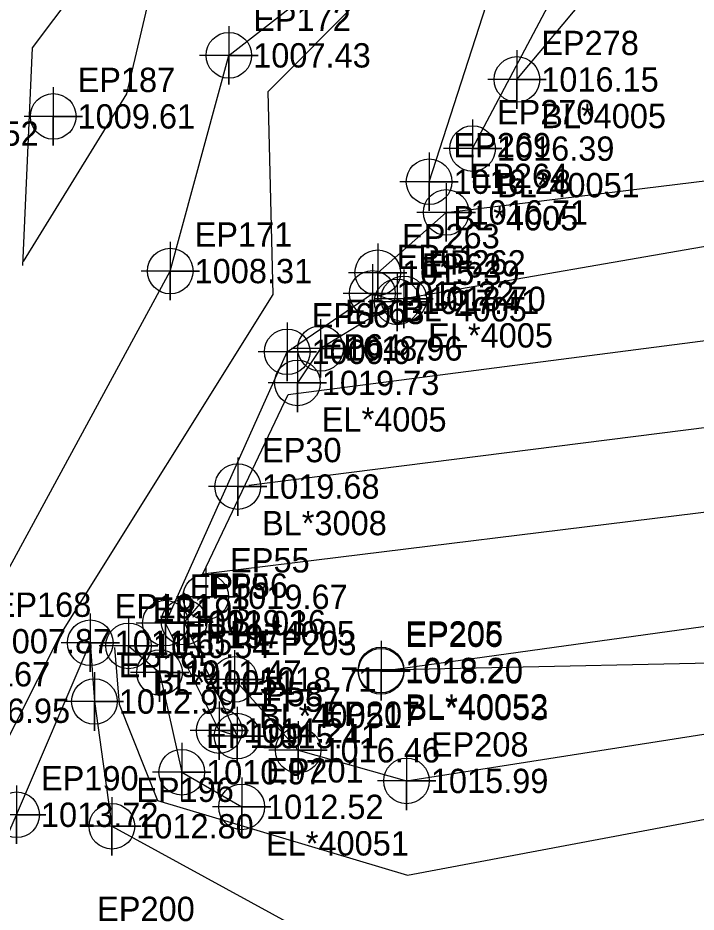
# Model space of a CAD drawing. Extents: x 1382561 to 1383039, y 884068 to 884307.
# Drawn here: x 1382794.3 to 1382864, y 884154.1 to 884246 of the extents above; entities that cross this region are included whole.
import ezdxf

# ---------------------------------------------------------------- set-up
doc = ezdxf.new("R2010")
doc.units = 0
for name, color, linetype in [('Exist DTM Breakline', 7, 'Continuous'), ('Exist DTM Breakline Cogo Comment', 7, 'Continuous'), ('Exist DTM Breakline Cogo Elevation', 7, 'Continuous'), ('Exist DTM Breakline Cogo Number', 7, 'Continuous'), ('Exist DTM Breakline Cogo Point CELL', 7, 'Continuous'), ('Exist DTM Breakline Underwater', 7, 'Continuous'), ('Exist DTM Breakline Underwater Cogo Elevation', 7, 'Continuous'), ('Exist DTM Breakline Underwater Cogo Number', 7, 'Continuous'), ('Exist DTM Breakline Underwater Cogo Point CELL', 7, 'Continuous'), ('Exist DTM Crownline', 7, 'Continuous'), ('Exist DTM Crownline Cogo Comment', 7, 'Continuous'), ('Exist DTM Crownline Cogo Elevation', 7, 'Continuous'), ('Exist DTM Crownline Cogo Number', 7, 'Continuous'), ('Exist DTM Crownline Cogo Point CELL', 7, 'Continuous'), ('Exist DTM Regular Point CELL', 7, 'Continuous'), ('Exist DTM Regular Point Cogo Elevation', 7, 'Continuous'), ('Exist DTM Regular Point Cogo Number', 7, 'Continuous'), ('Exist Hydro Stream or Body of Water', 7, 'Continuous'), ('Exist Roads EOP', 7, 'Continuous')]:
    doc.layers.add(name, color=color, linetype=linetype)

msp = doc.modelspace()

# ---------------------------------------------------------------- linework, layer by layer
at = {"layer": 'Exist DTM Breakline'}
msp.add_line((1382845.6099, 884239.6486), (1382877.4407, 884277.6733), dxfattribs=at)
for points in [[(1382836.5882, 884229.1511), (1382845.3839, 884256.4006), (1382857.665, 884285.1804)], [(1382841.0523, 884232.5474), (1382851.5055, 884252.2797), (1382873.9304, 884278.5226)], [(1382831.3079, 884219.8003), (1382838.3409, 884225.9989), (1382867.1646, 884229.517), (1382914.9927, 884234.9104), (1382969.1885, 884241.9138), (1383012.0651, 884249.1214)], [(1383012.5976, 884239.5988), (1382967.445, 884235.5084), (1382916.3525, 884229.3577), (1382867.9342, 884223.0248), (1382833.9892, 884217.1167)], [(1382813.6347, 884186.5142), (1382811.4039, 884183.9166), (1382816.8445, 884172.2048), (1382815.0173, 884172.7731), (1382809.4772, 884183.8181), (1382822.0049, 884211.6766), (1382830.7533, 884217.6734), (1382833.3088, 884216.8097), (1382825.4375, 884212.0253), (1382823.0555, 884208.4903)], [(1382831.6499, 884178.864), (1382874.1379, 884184.7558), (1382926.2901, 884192.0506), (1382972.0132, 884197.818), (1383015.5779, 884204.7229)], [(1382833.366, 884179.0369), (1382875.2238, 884179.95), (1382925.7486, 884188.0979), (1382971.8534, 884193.2925), (1383016.146, 884199.3057)], [(1382816.5885, 884178.0325), (1382823.1269, 884170.7527), (1382834.2668, 884167.6062), (1382876.3893, 884174.2104), (1382925.471, 884179.9339), (1382972.4064, 884189.3415), (1383016.1626, 884195.7946)], [(1382751.4287, 884075.9856), (1382771.8716, 884111.3375), (1382784.8942, 884142.8663), (1382794.19, 884164.1279), (1382801.7626, 884181.793), (1382802.1903, 884175.7622), (1382803.9822, 884162.9447), (1382834.7331, 884146.1448), (1382885.2227, 884156.817), (1382912.2708, 884159.0791), (1382962.484, 884168.5252), (1383014.0488, 884181.852)], [(1382805.6901, 884181.4753), (1382808.8901, 884178.7339), (1382811.1624, 884168.5017), (1382817.3226, 884164.9432)]]:
    msp.add_lwpolyline(points, dxfattribs=at)
at = {"layer": 'Exist DTM Breakline Cogo Point CELL'}
for points in [[(1382845.6099, 884242.6486), (1382845.6099, 884236.6486), (1382845.6099, 884239.6486), (1382848.6099, 884239.6486), (1382842.6099, 884239.6486)], [(1382841.0523, 884235.5474), (1382841.0523, 884229.5474), (1382841.0523, 884232.5474), (1382844.0523, 884232.5474), (1382838.0523, 884232.5474)], [(1382836.5882, 884232.1511), (1382836.5882, 884226.1511), (1382836.5882, 884229.1511), (1382839.5882, 884229.1511), (1382833.5882, 884229.1511)], [(1382838.3409, 884228.9989), (1382838.3409, 884222.9989), (1382838.3409, 884225.9989), (1382841.3409, 884225.9989), (1382835.3409, 884225.9989)], [(1382831.3079, 884222.8003), (1382831.3079, 884216.8003), (1382831.3079, 884219.8003), (1382834.3079, 884219.8003), (1382828.3079, 884219.8003)], [(1382830.7533, 884220.6734), (1382830.7533, 884214.6734), (1382830.7533, 884217.6734), (1382833.7533, 884217.6734), (1382827.7533, 884217.6734)], [(1382833.3088, 884219.8097), (1382833.3088, 884213.8097), (1382833.3088, 884216.8097), (1382836.3088, 884216.8097), (1382830.3088, 884216.8097)], [(1382833.9892, 884220.1167), (1382833.9892, 884214.1167), (1382833.9892, 884217.1167), (1382836.9892, 884217.1167), (1382830.9892, 884217.1167)], [(1382822.0049, 884214.6766), (1382822.0049, 884208.6766), (1382822.0049, 884211.6766), (1382825.0049, 884211.6766), (1382819.0049, 884211.6766)], [(1382825.4375, 884215.0253), (1382825.4375, 884209.0253), (1382825.4375, 884212.0253), (1382828.4375, 884212.0253), (1382822.4375, 884212.0253)], [(1382823.0555, 884211.4903), (1382823.0555, 884205.4903), (1382823.0555, 884208.4903), (1382826.0555, 884208.4903), (1382820.0555, 884208.4903)], [(1382813.6347, 884189.5142), (1382813.6347, 884183.5142), (1382813.6347, 884186.5142), (1382816.6347, 884186.5142), (1382810.6347, 884186.5142)], [(1382809.4772, 884186.8181), (1382809.4772, 884180.8181), (1382809.4772, 884183.8181), (1382812.4772, 884183.8181), (1382806.4772, 884183.8181)], [(1382811.4039, 884186.9166), (1382811.4039, 884180.9166), (1382811.4039, 884183.9166), (1382814.4039, 884183.9166), (1382808.4039, 884183.9166)], [(1382801.7626, 884184.793), (1382801.7626, 884178.793), (1382801.7626, 884181.793), (1382804.7626, 884181.793), (1382798.7626, 884181.793)], [(1382805.6901, 884184.4753), (1382805.6901, 884178.4753), (1382805.6901, 884181.4753), (1382808.6901, 884181.4753), (1382802.6901, 884181.4753)], [(1382808.8901, 884181.7339), (1382808.8901, 884175.7339), (1382808.8901, 884178.7339), (1382811.8901, 884178.7339), (1382805.8901, 884178.7339)], [(1382831.6443, 884181.9993), (1382831.6443, 884175.9993), (1382831.6443, 884178.9993), (1382834.6443, 884178.9993), (1382828.6443, 884178.9993)], [(1382831.6499, 884181.864), (1382831.6499, 884175.864), (1382831.6499, 884178.864), (1382834.6499, 884178.864), (1382828.6499, 884178.864)], [(1382816.5885, 884181.0325), (1382816.5885, 884175.0325), (1382816.5885, 884178.0325), (1382819.5885, 884178.0325), (1382813.5885, 884178.0325)], [(1382802.1903, 884178.7622), (1382802.1903, 884172.7622), (1382802.1903, 884175.7622), (1382805.1903, 884175.7622), (1382799.1903, 884175.7622)], [(1382815.0173, 884175.7731), (1382815.0173, 884169.7731), (1382815.0173, 884172.7731), (1382818.0173, 884172.7731), (1382812.0173, 884172.7731)], [(1382816.8445, 884175.2048), (1382816.8445, 884169.2048), (1382816.8445, 884172.2048), (1382819.8445, 884172.2048), (1382813.8445, 884172.2048)], [(1382823.1269, 884173.7527), (1382823.1269, 884167.7527), (1382823.1269, 884170.7527), (1382826.1269, 884170.7527), (1382820.1269, 884170.7527)], [(1382811.1624, 884171.5017), (1382811.1624, 884165.5017), (1382811.1624, 884168.5017), (1382814.1624, 884168.5017), (1382808.1624, 884168.5017)], [(1382834.2668, 884170.6062), (1382834.2668, 884164.6062), (1382834.2668, 884167.6062), (1382837.2668, 884167.6062), (1382831.2668, 884167.6062)], [(1382817.3226, 884167.9432), (1382817.3226, 884161.9432), (1382817.3226, 884164.9432), (1382820.3226, 884164.9432), (1382814.3226, 884164.9432)], [(1382794.19, 884167.1279), (1382794.19, 884161.1279), (1382794.19, 884164.1279), (1382797.19, 884164.1279), (1382791.19, 884164.1279)], [(1382803.9822, 884165.9447), (1382803.9822, 884159.9447), (1382803.9822, 884162.9447), (1382806.9822, 884162.9447), (1382800.9822, 884162.9447)]]:
    msp.add_lwpolyline(points, dxfattribs=at)
for centre in [(1382845.6099, 884239.6486), (1382841.0523, 884232.5474), (1382836.5882, 884229.1511), (1382838.3409, 884225.9989), (1382831.3079, 884219.8003), (1382830.7533, 884217.6734), (1382833.3088, 884216.8097), (1382833.9892, 884217.1167), (1382825.4375, 884212.0253), (1382822.0049, 884211.6766), (1382823.0555, 884208.4903), (1382813.6347, 884186.5142), (1382809.4772, 884183.8181), (1382811.4039, 884183.9166), (1382801.7626, 884181.793), (1382805.6901, 884181.4753), (1382831.6443, 884178.9993), (1382831.6499, 884178.864), (1382808.8901, 884178.7339), (1382816.5885, 884178.0325), (1382802.1903, 884175.7622), (1382815.0173, 884172.7731), (1382816.8445, 884172.2048), (1382823.1269, 884170.7527), (1382811.1624, 884168.5017), (1382834.2668, 884167.6062), (1382817.3226, 884164.9432), (1382794.19, 884164.1279), (1382803.9822, 884162.9447)]:
    msp.add_circle(centre, 2.344, dxfattribs=at)
at = {"layer": 'Exist DTM Breakline Underwater'}
msp.add_lwpolyline([(1382688.3783, 884086.9383), (1382699.504, 884112.5821), (1382721.2073, 884133.5617), (1382743.6214, 884142.6712), (1382769.5658, 884160.0329), (1382785.1067, 884174.8132), (1382789.3291, 884181.9565), (1382809.982, 884219.9732), (1382816.0046, 884242.1273), (1382837.3981, 884258.7844), (1382845.6113, 884276.5289)], dxfattribs=at)
at = {"layer": 'Exist DTM Breakline Underwater Cogo Point CELL'}
for points in [[(1382816.0046, 884245.1273), (1382816.0046, 884239.1273), (1382816.0046, 884242.1273), (1382819.0046, 884242.1273), (1382813.0046, 884242.1273)], [(1382809.982, 884222.9732), (1382809.982, 884216.9732), (1382809.982, 884219.9732), (1382812.982, 884219.9732), (1382806.982, 884219.9732)]]:
    msp.add_lwpolyline(points, dxfattribs=at)
for centre in [(1382816.0046, 884242.1273), (1382809.982, 884219.9732)]:
    msp.add_circle(centre, 2.344, dxfattribs=at)
at = {"layer": 'Exist DTM Crownline'}
msp.add_lwpolyline([(1382818.0568, 884197.9832), (1382870.8354, 884204.6592), (1382920.1217, 884211.0486), (1382969.977, 884216.8417), (1383014.7296, 884222.2543)], dxfattribs=at)
at = {"layer": 'Exist DTM Crownline Cogo Point CELL'}
msp.add_lwpolyline([(1382816.9119, 884200.8384), (1382816.9119, 884194.8384), (1382816.9119, 884197.8384), (1382819.9119, 884197.8384), (1382813.9119, 884197.8384)], dxfattribs=at)
msp.add_circle((1382816.9119, 884197.8384), 2.344, dxfattribs=at)
at = {"layer": 'Exist DTM Regular Point CELL'}
msp.add_lwpolyline([(1382797.9522, 884238.8572), (1382797.9522, 884232.8572), (1382797.9522, 884235.8572), (1382800.9522, 884235.8572), (1382794.9522, 884235.8572)], dxfattribs=at)
msp.add_circle((1382797.9522, 884235.8572), 2.344, dxfattribs=at)
at = {"layer": 'Exist Hydro Stream or Body of Water'}
for points in [[(1382697.0874, 884084.7019), (1382707.0296, 884107.5273), (1382718.101, 884120.6229), (1382747.1797, 884135.9958), (1382776.4132, 884151.3238), (1382791.7634, 884168.9711), (1382798.6691, 884182.5745), (1382820.5432, 884217.5751), (1382820.037, 884238.4145), (1382839.3094, 884257.7694), (1382850.1603, 884274.5827)], [(1382811.148, 884263.3209), (1382795.7798, 884242.8831), (1382794.8118, 884220.542)], [(1382811.3728, 884263.1874), (1382805.484, 884238.1799), (1382794.8471, 884220.9683)], [(1382804.2469, 884181.3186), (1382804.7285, 884175.5016), (1382808.6563, 884165.6118), (1382834.3787, 884157.9417), (1382885.1736, 884167.4669), (1382917.5577, 884168.9128), (1382957.8255, 884179.6802), (1383014.491, 884188.8061)]]:
    msp.add_lwpolyline(points, dxfattribs=at)
at = {"layer": 'Exist Roads EOP'}
for points in [[(1382822.1133, 884207.287), (1382869.4756, 884213.4311), (1382919.3634, 884219.5355), (1382969.3733, 884225.6957), (1383013.6331, 884231.1593)], [(1382813.3303, 884188.8665), (1382871.1957, 884195.987), (1382921.2905, 884202.1311), (1382970.8421, 884208.1022), (1383015.6768, 884213.5139)], [(1382813.3303, 884188.8665), (1382822.1133, 884207.287)]]:
    msp.add_lwpolyline(points, dxfattribs=at)

# ---------------------------------------------------------------- texts
at = {"layer": 'Exist DTM Breakline Cogo Comment'}
for s, p in [('BL*4005', (1382848.1099, 884234.6486)), ('BL*40051', (1382843.5523, 884227.5474)), ('BL*4005', (1382839.0882, 884224.1511)), ('BL*4005', (1382833.8079, 884214.8003)), ('EL*4005', (1382836.4892, 884212.1167)), ('EL*4005', (1382825.5555, 884203.4903)), ('BL*4005', (1382816.1347, 884181.5142)), ('BL*40051', (1382808.1901, 884176.4753)), ('BL*40052', (1382834.1443, 884173.9993)), ('BL*40053', (1382834.1499, 884173.864)), ('BL*40051', (1382819.0885, 884173.0325)), ('EL*40051', (1382819.8226, 884159.9432))]:
    msp.add_text(s, height=2.5, dxfattribs=at).set_placement(p)
at = {"layer": 'Exist DTM Breakline Cogo Elevation'}
for s, p in [('1016.15', (1382848.1099, 884238.3986)), ('1014.52', (1382784.3725, 884232.8418)), ('1016.39', (1382843.5523, 884231.2974)), ('1016.28', (1382839.0882, 884227.9011)), ('1016.71', (1382840.8409, 884224.7489)), ('1015.39', (1382833.8079, 884218.5503)), ('1015.22', (1382833.2533, 884216.4234)), ('1017.41', (1382835.8088, 884215.5597)), ('1018.70', (1382836.4892, 884215.8667)), ('1009.97', (1382824.5049, 884210.4266)), ('1018.96', (1382827.9375, 884210.7753)), ('1019.73', (1382825.5555, 884207.2403)), ('1019.67', (1382816.1347, 884185.2642)), ('1012.03', (1382811.9772, 884182.5681)), ('1019.16', (1382813.9039, 884182.6666)), ('1011.65', (1382804.2626, 884180.543)), ('1010.54', (1382808.1901, 884180.2253)), ('1018.20', (1382834.1443, 884177.7493)), ('1011.47', (1382811.3901, 884177.4839)), ('1018.20', (1382834.1499, 884177.614)), ('1018.71', (1382819.0885, 884176.7825)), ('1012.99', (1382804.6903, 884174.5122)), ('1014.21', (1382817.5173, 884171.5231)), ('1015.41', (1382819.3445, 884170.9548)), ('1016.46', (1382825.6269, 884169.5027)), ('1010.97', (1382813.6624, 884167.2517)), ('1015.99', (1382836.7668, 884166.3562)), ('1012.52', (1382819.8226, 884163.6932)), ('1013.72', (1382796.69, 884162.8779)), ('1012.80', (1382806.4822, 884161.6947))]:
    msp.add_text(s, height=2.5, dxfattribs=at).set_placement(p)
at = {"layer": 'Exist DTM Breakline Cogo Number'}
for s, p in [('EP278', (1382848.1099, 884242.1486)), ('EP270', (1382843.5523, 884235.0474)), ('EP269', (1382839.0882, 884231.6511)), ('EP264', (1382840.8409, 884228.4989)), ('EP263', (1382833.8079, 884222.3003)), ('EP61', (1382833.2533, 884220.1734)), ('EP62', (1382835.8088, 884219.3097)), ('EP262', (1382836.4892, 884219.6167)), ('EP63', (1382827.9375, 884214.5253)), ('EP60', (1382824.5049, 884214.1766)), ('EP64', (1382825.5555, 884210.9903)), ('EP55', (1382816.1347, 884189.0142)), ('EP59', (1382811.9772, 884186.3181)), ('EP56', (1382813.9039, 884186.4166)), ('EP191', (1382804.2626, 884184.293)), ('EP193', (1382808.1901, 884183.9753)), ('EP205', (1382834.1443, 884181.4993)), ('EP197', (1382811.3901, 884181.2339)), ('EP203', (1382819.0885, 884180.5325)), ('EP206', (1382834.1499, 884181.364)), ('EP195', (1382804.6903, 884178.2622)), ('EP58', (1382817.5173, 884175.2731)), ('EP57', (1382819.3445, 884174.7048)), ('EP207', (1382825.6269, 884173.2527)), ('EP199', (1382813.6624, 884171.0017)), ('EP208', (1382836.7668, 884170.1062)), ('EP201', (1382819.8226, 884167.4432)), ('EP190', (1382796.69, 884166.6279)), ('EP196', (1382806.4822, 884165.4447))]:
    msp.add_text(s, height=2.5, dxfattribs=at).set_placement(p)
at = {"layer": 'Exist DTM Breakline Underwater Cogo Elevation'}
for s, p in [('1007.43', (1382818.5046, 884240.8773)), ('1008.31', (1382812.482, 884218.7232)), ('1007.87', (1382791.8291, 884180.7065)), ('1006.95', (1382787.6067, 884173.5632))]:
    msp.add_text(s, height=2.5, dxfattribs=at).set_placement(p)
at = {"layer": 'Exist DTM Breakline Underwater Cogo Number'}
for s, p in [('EP172', (1382818.5046, 884244.6273)), ('EP171', (1382812.482, 884222.4732)), ('EP168', (1382791.8291, 884184.4565)), ('EP167', (1382787.6067, 884177.3132))]:
    msp.add_text(s, height=2.5, dxfattribs=at).set_placement(p)
at = {"layer": 'Exist DTM Crownline Cogo Comment'}
msp.add_text('BL*3008', height=2.5, dxfattribs=at).set_placement((1382819.4119, 884192.8384))
at = {"layer": 'Exist DTM Crownline Cogo Elevation'}
msp.add_text('1019.68', height=2.5, dxfattribs=at).set_placement((1382819.4119, 884196.5884))
at = {"layer": 'Exist DTM Crownline Cogo Number'}
msp.add_text('EP30', height=2.5, dxfattribs=at).set_placement((1382819.4119, 884200.3384))
at = {"layer": 'Exist DTM Regular Point Cogo Elevation'}
msp.add_text('1009.61', height=2.5, dxfattribs=at).set_placement((1382800.4522, 884234.6072))
at = {"layer": 'Exist DTM Regular Point Cogo Number'}
for s, p in [('EP187', (1382800.4522, 884238.3572)), ('EP200', (1382802.4651, 884153.2126))]:
    msp.add_text(s, height=2.5, dxfattribs=at).set_placement(p)

doc.saveas('drawing.dxf')
